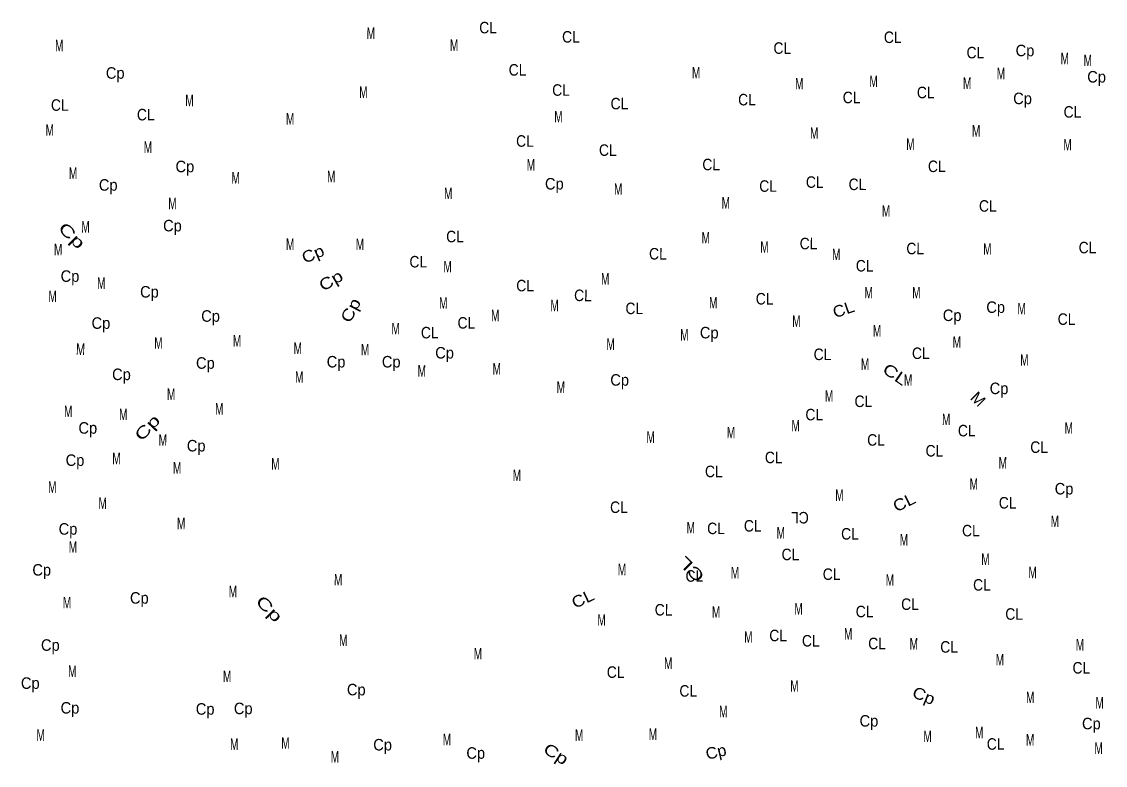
# Model space of a CAD drawing. Extents: x 713577 to 726626, y 7177731 to 7191794.
# Drawn here: x 713590 to 717165, y 7180461 to 7182914 of the extents above; entities that cross this region are included whole.
import ezdxf
from ezdxf.enums import TextEntityAlignment as Align

# ---------------------------------------------------------------- set-up
doc = ezdxf.new("R2010")
doc.units = 0
doc.header["$LTSCALE"] = 15
doc.layers.add('19', color=7, linetype='Continuous')

msp = doc.modelspace()

# ---------------------------------------------------------------- texts
at = {"layer": '19'}
for s, rotation, width, p in [('CL', 359.905, 0.9, (715128.24, 7182875.69)), ('M', 359.905, 0.65, (714741.44, 7182857.24)), ('CL', 359.905, 0.9, (715401.56, 7182845.3)), ('CL', 359.905, 0.9, (716463.21, 7182843.88)), ('M', 359.905, 0.65, (713713.34, 7182816.59)), ('M', 359.905, 0.65, (715016.12, 7182818.07)), ('CL', 359.905, 0.9, (716098.89, 7182808.23)), ('CL', 359.905, 0.9, (716735.84, 7182793.26)), ('Cp', 359.905, 0.95, (716899.46, 7182800.24)), ('M', 359.99, 0.65, (717030.71, 7182774.11)), ('M', 359.99, 0.65, (717106.72, 7182767.84)), ('Cp', 359.905, 0.95, (713898.11, 7182726)), ('CL', 359.905, 0.9, (715225.45, 7182736.33)), ('M', 359.905, 0.65, (715814.52, 7182727.3)), ('M', 359.905, 0.65, (716820.16, 7182724.5)), ('M', 359.905, 0.65, (716154.78, 7182690.82)), ('M', 359.905, 0.65, (716400.03, 7182698.62)), ('M', 359.905, 0.65, (716708.61, 7182692.36)), ('Cp', 359.99, 0.95, (717135.67, 7182713.54)), ('M', 359.905, 0.65, (714716.93, 7182662.81)), ('CL', 359.905, 0.9, (715368.84, 7182669.81)), ('CL', 359.905, 0.9, (716572.02, 7182661.74)), ('CL', 359.905, 0.9, (713715.34, 7182620.26)), ('M', 359.905, 0.65, (714143.21, 7182635.59)), ('CL', 359.905, 0.9, (715561.61, 7182625.11)), ('CL', 359.905, 0.9, (715982.32, 7182638.09)), ('CL', 359.905, 0.9, (716327.44, 7182645.39)), ('Cp', 359.905, 0.95, (716891.45, 7182642.18)), ('CL', 359.905, 0.9, (713998.98, 7182588.63)), ('M', 359.905, 0.65, (714475.18, 7182575.05)), ('M', 359.905, 0.65, (715360.4, 7182581.87)), ('CL', 359.99, 0.9, (717056.14, 7182597.72)), ('M', 359.905, 0.65, (713682.05, 7182537.92)), ('M', 359.905, 0.65, (716204.11, 7182527.94)), ('M', 359.905, 0.65, (716738.37, 7182535.29)), ('M', 359.905, 0.65, (714006.08, 7182481.38)), ('CL', 359.905, 0.9, (715249.91, 7182501.65)), ('CL', 359.905, 0.9, (715523.28, 7182471.7)), ('M', 359.905, 0.65, (716521.45, 7182491.15)), ('M', 359.99, 0.65, (717039.87, 7182489.46)), ('Cp', 359.905, 0.95, (714128, 7182417.67)), ('M', 359.905, 0.65, (715269.33, 7182422.94)), ('CL', 359.905, 0.9, (715864.31, 7182424.18)), ('CL', 359.905, 0.9, (716608.55, 7182418.16)), ('M', 359.905, 0.65, (713759.04, 7182395.62)), ('M', 359.905, 0.65, (714295.57, 7182380.15)), ('M', 359.905, 0.65, (714610.75, 7182384.6)), ('Cp', 359.905, 0.95, (715346.77, 7182360.64)), ('CL', 359.905, 0.9, (716205.9, 7182366.15)), ('Cp', 359.905, 0.95, (713875.03, 7182356.78)), ('M', 359.905, 0.65, (714996.75, 7182328.94)), ('M', 359.905, 0.65, (715557.52, 7182343.26)), ('CL', 359.905, 0.9, (716051.97, 7182353.07)), ('CL', 359.905, 0.9, (716346.8, 7182358.74)), ('M', 359.905, 0.65, (714086.97, 7182295.65)), ('M', 359.905, 0.65, (715912.32, 7182297.89)), ('M', 359.905, 0.65, (716441.05, 7182271.02)), ('CL', 359.905, 0.9, (716776.89, 7182287.49)), ('M', 359.905, 0.65, (713800.17, 7182218.58)), ('Cp', 359.905, 0.95, (714086.91, 7182222.54)), ('Cp', 315, 1.5, (713741.56, 7182195.35)), ('CL', 359.905, 0.9, (715019.13, 7182186.53)), ('M', 359.905, 0.65, (715846.25, 7182182.71)), ('M', 359.905, 0.65, (714475.16, 7182161.12)), ('M', 359.905, 0.65, (714705.49, 7182161.07)), ('M', 359.905, 0.65, (716039.99, 7182151.98)), ('CL', 359.905, 0.9, (716185.38, 7182163.37)), ('CL', 359.905, 0.9, (716537.3, 7182147.05)), ('CL', 359.99, 0.9, (717105.76, 7182150.18)), ('M', 359.905, 0.65, (713709.9, 7182143.49)), ('Cp', 23.109, 1.15, (714558.02, 7182130.38)), ('CL', 359.905, 0.9, (715688.48, 7182129.74)), ('M', 359.905, 0.65, (716276.98, 7182127.64)), ('M', 359.905, 0.65, (716775.34, 7182145.63)), ('CL', 359.905, 0.9, (714898.02, 7182103.55)), ('M', 359.905, 0.65, (714994.69, 7182087.34)), ('CL', 359.905, 0.9, (716370.64, 7182090.21)), ('Cp', 359.905, 0.95, (713748.93, 7182056.07)), ('Cp', 30.666, 1.25, (714619.34, 7182044.17)), ('M', 359.905, 0.65, (715514.61, 7182047.04)), ('M', 359.905, 0.65, (713852.22, 7182032.9)), ('Cp', 359.905, 0.95, (714010.99, 7182004.27)), ('CL', 359.905, 0.9, (715250.51, 7182024.75)), ('M', 359.905, 0.65, (713691.42, 7181989.42)), ('M', 359.905, 0.65, (714980.57, 7181967.4)), ('CL', 358.264, 0.9, (715440.69, 7181992.28)), ('M', 359.905, 0.65, (715871.08, 7181968.57)), ('CL', 359.905, 0.9, (716040.53, 7181981.35)), ('M', 359.905, 0.65, (716383.82, 7182001.26)), ('M', 359.905, 0.65, (716541.16, 7182001.34)), ('Cp', 62.459, 1.25, (714691.8, 7181953.57)), ('M', 359.905, 0.65, (715347.43, 7181959.17)), ('CL', 359.905, 0.9, (715610.63, 7181949.58)), ('CL', 19.022, 1.1, (716306.85, 7181947.47)), ('Cp', 359.905, 0.95, (716802.72, 7181953.61)), ('M', 359.905, 0.65, (716888.48, 7181948.85)), ('Cp', 359.905, 0.95, (713851.08, 7181901.13)), ('Cp', 359.905, 0.95, (714212.69, 7181924.39)), ('CL', 359.905, 0.9, (715056.77, 7181901.78)), ('M', 359.905, 0.65, (715151.85, 7181926.35)), ('M', 359.905, 0.65, (716145.35, 7181907.61)), ('CL', 359.99, 0.9, (717036.61, 7181914.24)), ('M', 359.905, 0.65, (714823.34, 7181882.82)), ('CL', 359.905, 0.9, (714935.75, 7181869.51)), ('M', 359.905, 0.65, (715775.75, 7181862.16)), ('Cp', 359.905, 0.95, (715857.82, 7181869.51)), ('M', 359.905, 0.65, (716411.32, 7181875.35)), ('M', 359.905, 0.65, (714040.8, 7181835.4)), ('M', 359.905, 0.65, (714299.98, 7181842.26)), ('M', 359.905, 0.65, (715532.45, 7181831.74)), ('M', 359.905, 0.65, (716674.62, 7181838.65)), ('M', 358.264, 0.7, (713783.26, 7181815.27)), ('M', 359.905, 0.65, (714500.44, 7181818.06)), ('M', 359.905, 0.65, (714722.48, 7181813.39)), ('Cp', 359.905, 0.95, (714984.68, 7181803.14)), ('CL', 359.905, 0.9, (716231.55, 7181797.97)), ('CL', 359.905, 0.9, (716555.88, 7181801.57)), ('Cp', 359.905, 0.95, (714195.53, 7181769.32)), ('Cp', 359.905, 0.95, (714626.7, 7181773.58)), ('Cp', 359.905, 0.95, (714808.65, 7181773.61)), ('M', 359.905, 0.65, (716371.8, 7181765.72)), ('M', 359.905, 0.65, (716897.44, 7181779.28)), ('Cp', 359.905, 0.95, (713918.74, 7181732)), ('M', 359.905, 0.65, (714505.22, 7181723.41)), ('M', 359.905, 0.65, (714909.58, 7181743.29)), ('M', 359.905, 0.65, (715156.82, 7181750.17)), ('CL', 325.749, 1.3, (716460.7, 7181735.49)), ('M', 359.905, 0.65, (715368.16, 7181689.5)), ('Cp', 359.905, 0.95, (715562.28, 7181713.57)), ('M', 359.905, 0.65, (716514, 7181713.4)), ('Cp', 359.905, 0.95, (716813.82, 7181685.73)), ('M', 359.905, 0.65, (714082.61, 7181666.64)), ('M', 359.905, 0.65, (716252.98, 7181660.53)), ('M', 359.905, 0.65, (713743.15, 7181610.2)), ('M', 359.905, 0.65, (714241.28, 7181618.32)), ('CL', 359.905, 0.9, (716366.31, 7181643.11)), ('M', 359.905, 0.65, (713924.75, 7181599.95)), ('CL', 359.905, 0.9, (716204.37, 7181599.17)), ('M', 359.905, 0.65, (716639.48, 7181583.43)), ('Cp', 359.905, 0.95, (713807.75, 7181555.21)), ('Cp', 46.693, 1.45, (714017.78, 7181561.97)), ('M', 359.905, 0.65, (715929.66, 7181539.77)), ('M', 359.905, 0.65, (716142.79, 7181562.61)), ('CL', 359.905, 0.9, (716707.38, 7181546.37)), ('M', 359.99, 0.65, (717043.79, 7181554.9)), ('M', 359.905, 0.65, (714055.18, 7181515.23)), ('M', 359.905, 0.65, (715664.5, 7181524.96)), ('CL', 359.905, 0.9, (716408.05, 7181515.64)), ('Cp', 359.905, 0.95, (714165.25, 7181496.62)), ('CL', 359.905, 0.9, (716600.72, 7181479.91)), ('CL', 359.905, 0.9, (716946.12, 7181491.88)), ('Cp', 359.905, 0.95, (713765.49, 7181448.9)), ('M', 359.905, 0.65, (713902.3, 7181454.5)), ('M', 359.905, 0.65, (714426.53, 7181436.54)), ('CL', 359.905, 0.9, (716070.58, 7181457.87)), ('M', 359.905, 0.65, (716826.28, 7181440.28)), ('M', 359.905, 0.65, (714102.42, 7181423.35)), ('M', 359.905, 0.65, (715223.19, 7181399.1)), ('CL', 359.905, 0.9, (715872.98, 7181411.8)), ('M', 359.905, 0.65, (713690.7, 7181359.74)), ('M', 359.905, 0.65, (716730.5, 7181370.51)), ('M', 359.905, 0.65, (716287.24, 7181333.7)), ('Cp', 359.99, 0.95, (717028.37, 7181354.77)), ('M', 359.905, 0.65, (713856.65, 7181306.77)), ('CL', 359.905, 0.9, (715559.93, 7181293.68)), ('CL', 25.905, 1.15, (716509.15, 7181311.99)), ('CL', 359.905, 0.9, (716842.24, 7181308.31)), ('CL', 180, 0.9, (716157.07, 7181297.22)), ('Cp', 359.905, 0.95, (713742.41, 7181222.06)), ('M', 359.905, 0.65, (714115.67, 7181240.2)), ('M', 359.905, 0.65, (715796.9, 7181226.47)), ('CL', 359.905, 0.9, (715880.29, 7181223.88)), ('CL', 359.905, 0.9, (716001.27, 7181232.3)), ('CL', 359.905, 0.9, (716721.02, 7181216.47)), ('M', 359.99, 0.65, (716997.99, 7181247.23)), ('M', 359.905, 0.65, (716093.82, 7181209.41)), ('CL', 359.905, 0.9, (716322.04, 7181205.92)), ('M', 359.905, 0.65, (716500.09, 7181186.2)), ('M', 359.905, 0.65, (713758.61, 7181162.58)), ('CL', 135, 1.45, (715812.1, 7181121.06)), ('CL', 359.905, 0.9, (716125.73, 7181137.97)), ('M', 359.905, 0.65, (716769.01, 7181122.38)), ('Cp', 359.905, 0.95, (713655.68, 7181086.99)), ('M', 359.905, 0.65, (715569.99, 7181087.99)), ('M', 359.905, 0.65, (715942.81, 7181077.43)), ('M', 359.99, 0.65, (716924.64, 7181078.69)), ('M', 359.905, 0.65, (714633.69, 7181054.74)), ('CL', 359.905, 0.9, (715808.78, 7181066.91)), ('CL', 359.905, 0.9, (716261.5, 7181072.79)), ('M', 359.905, 0.65, (716453.81, 7181053.71)), ('CL', 359.99, 0.9, (716757.51, 7181037.53)), ('M', 359.905, 0.65, (714286.31, 7181015.55)), ('M', 359.905, 0.65, (713739.09, 7180978.67)), ('Cp', 359.905, 0.95, (713977.73, 7180994.52)), ('Cp', 314.188, 1.5, (714392.47, 7180964.28)), ('CL', 25.385, 1.15, (715448.78, 7180993.36)), ('CL', 359.905, 0.9, (716520.17, 7180973.93)), ('CL', 359.905, 0.9, (715707.18, 7180955.39)), ('M', 359.905, 0.65, (715880.29, 7180948.28)), ('M', 359.905, 0.65, (716152.4, 7180958.77)), ('CL', 359.905, 0.9, (716370.33, 7180949.65)), ('CL', 359.905, 0.9, (716863.73, 7180941.45)), ('M', 359.905, 0.65, (715502.77, 7180921.73)), ('M', 359.905, 0.65, (715986.87, 7180865.58)), ('CL', 359.905, 0.9, (716085.18, 7180870.59)), ('M', 359.905, 0.65, (716316.31, 7180876.3)), ('Cp', 359.905, 0.95, (713684.11, 7180839.04)), ('M', 359.905, 0.65, (714650.6, 7180854.87)), ('CL', 359.905, 0.9, (716192.86, 7180853.18)), ('CL', 359.905, 0.9, (716411.58, 7180844.2)), ('M', 359.905, 0.65, (716532.67, 7180843.13)), ('CL', 359.905, 0.9, (716649.13, 7180832.94)), ('M', 359.99, 0.65, (717080.91, 7180840.08)), ('M', 359.905, 0.65, (715094.62, 7180810.72)), ('M', 359.905, 0.65, (716816.63, 7180790.77)), ('M', 359.905, 0.65, (713756.61, 7180752.62)), ('M', 359.905, 0.65, (715722.59, 7180779.19)), ('CL', 359.905, 0.9, (717085.49, 7180764.04)), ('CL', 359.905, 0.9, (717085.49, 7180764.04)), ('M', 359.905, 0.65, (714267.29, 7180735.87)), ('CL', 359.905, 0.9, (715549.09, 7180749.85)), ('Cp', 359.905, 0.95, (713617.95, 7180713.55)), ('Cp', 359.905, 0.95, (714693.41, 7180692.08)), ('CL', 359.905, 0.9, (715788.6, 7180687.81)), ('M', 359.905, 0.65, (716138.88, 7180704.06)), ('Cp', 337.537, 1.15, (716558.68, 7180673.7)), ('M', 359.905, 0.65, (716916.7, 7180666.57)), ('M', 359.99, 0.65, (717145.7, 7180648.55)), ('Cp', 359.905, 0.95, (713748.79, 7180632)), ('Cp', 359.905, 0.95, (714194.86, 7180628.28)), ('Cp', 359.905, 0.95, (714320.47, 7180630.06)), ('M', 359.905, 0.65, (715904.27, 7180619.81)), ('Cp', 359.905, 0.95, (716384.6, 7180588.98)), ('Cp', 359.99, 0.95, (717118.42, 7180580.06)), ('M', 359.905, 0.65, (713652.2, 7180542.02)), ('M', 359.905, 0.65, (715428.57, 7180542.05)), ('M', 359.905, 0.65, (715671.83, 7180544.97)), ('M', 359.905, 0.65, (716577.96, 7180538.12)), ('M', 359.99, 0.65, (716748.54, 7180550.51)), ('M', 359.905, 0.65, (714290.78, 7180512.13)), ('M', 359.905, 0.65, (714459.8, 7180515.82)), ('Cp', 359.905, 0.95, (714780.27, 7180510.32)), ('M', 359.905, 0.65, (714992.4, 7180527.53)), ('CL', 359.905, 0.9, (716802.65, 7180512.71)), ('M', 359.905, 0.65, (716916.47, 7180526.7)), ('M', 359.905, 0.65, (714622.78, 7180470.48)), ('Cp', 359.905, 0.95, (715087.44, 7180482.97)), ('Cp', 327.515, 1.3, (715342.31, 7180482.99)), ('Cp', 13.568, 1.05, (715884.47, 7180487.25)), ('M', 359.99, 0.65, (717142.41, 7180498.84))]:
    msp.add_text(s, height=38, rotation=rotation, dxfattribs=dict(at, width=width)).set_placement(p, align=Align.CENTER)
at = {"layer": '19', "width": 0.95}
msp.add_text('Cp', height=38, dxfattribs=at).set_placement((716659.18, 7181926.8), align=Align.CENTER)
at = {"layer": '19'}
msp.add_text('M', height=38, rotation=315, dxfattribs=at).set_placement((716731.2, 7181655.66), align=Align.CENTER)

doc.saveas('drawing.dxf')
